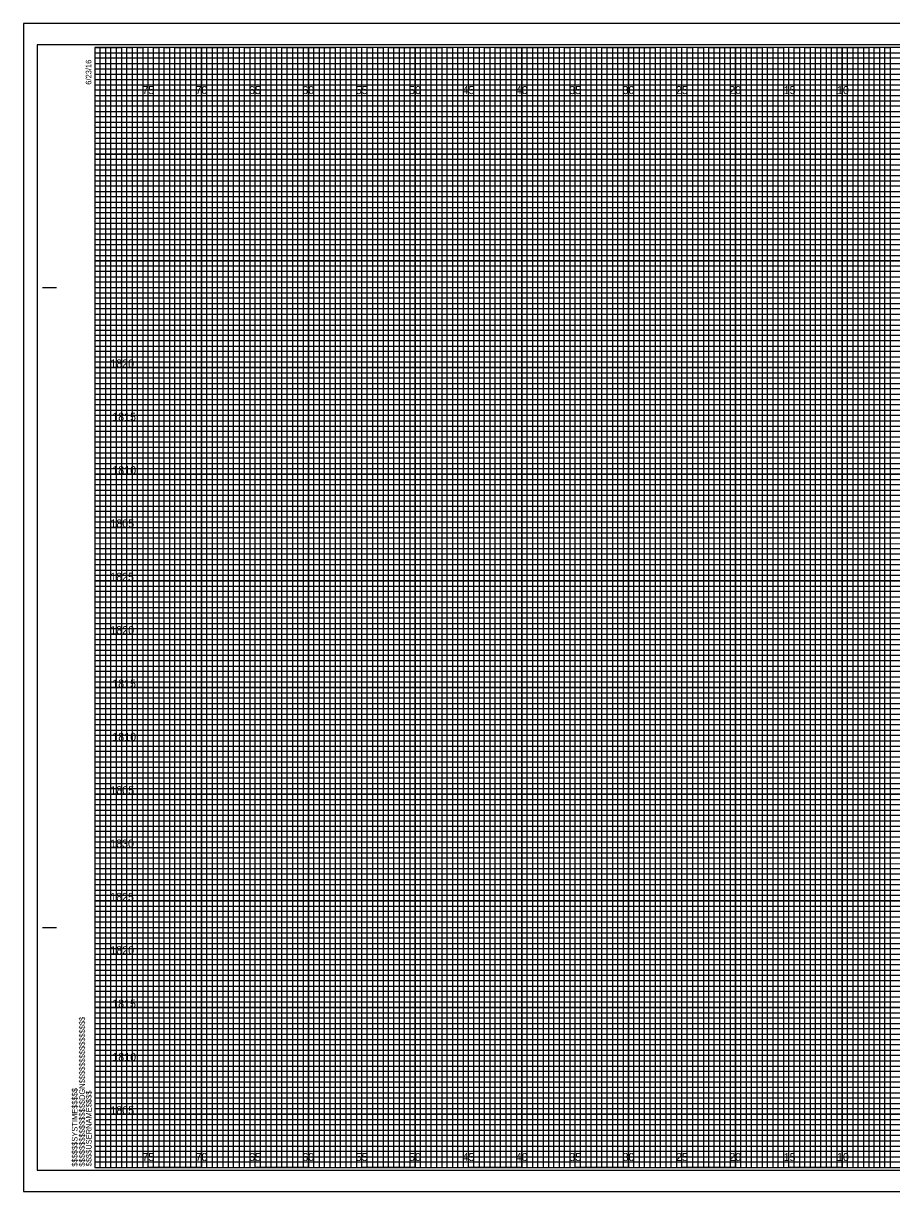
# Model space of a CAD drawing. Extents: x -7 to 392, y -2 to 440.
# Drawn here: x -6.7 to 74.6, y -2.3 to 107.3 of the extents above; entities that cross this region are included whole.
import ezdxf

# ---------------------------------------------------------------- set-up
doc = ezdxf.new("R2010")
doc.units = 0
for name, color, linetype in [('Prop Grid Mask', 7, 'Continuous'), ('Prop XS Elevation Labels', 7, 'Continuous'), ('Sheet Cross Section CELL', 7, 'Continuous'), ('Sheet Cross Section Grid Major CELL', 7, 'Continuous'), ('Sheet Cross Section Grid Middle CELL', 7, 'Continuous'), ('Sheet Cross Section Grid Minor 1 CELL', 7, 'Continuous'), ('Sheet Cross Section Grid Minor 2 CELL', 7, 'Continuous'), ('Sheet Cutting Line CELL', 7, 'Continuous'), ('Sheet DOT Grid CELL', 7, 'Continuous'), ('Sheet Plot Border Inside CELL', 7, 'Continuous'), ('Sheet Plot Border Outside CELL', 7, 'Continuous')]:
    doc.layers.add(name, color=color, linetype=linetype)

msp = doc.modelspace()

# ---------------------------------------------------------------- linework, layer by layer
at = {"layer": 'Sheet Cross Section CELL'}
for p, q in [((-4.9, 82.5), (-3.65, 82.5)), ((-4.85, 82.5), (-3.6, 82.5)), ((-4.9, 22.5), (-3.65, 22.5)), ((-4.85, 22.5), (-3.6, 22.5)), ((0, 0), (0, 0)), ((0, 0), (0, 0)), ((0, 0), (0, 0)), ((0, 0), (0, 0)), ((0, 0), (0, 0)), ((0, 0), (0, 0)), ((0, 0), (0, 0))]:
    msp.add_line(p, q, dxfattribs=at)
msp.add_lwpolyline([(160, 105), (0, 105), (0, 0), (160, 0)], close=True, dxfattribs=at)
at = {"layer": 'Sheet Cross Section Grid Major CELL'}
for p, q in [((5, 105), (0, 105)), ((5, 0), (5, 105)), ((15, 105), (10, 105)), ((10, 105), (10, 0)), ((15, 0), (15, 105)), ((25, 105), (20, 105)), ((20, 105), (20, 0)), ((25, 0), (25, 105)), ((35, 105), (30, 105)), ((30, 105), (30, 0)), ((35, 0), (35, 105)), ((45, 105), (40, 105)), ((40, 105), (40, 0)), ((45, 0), (45, 105)), ((55, 105), (50, 105)), ((50, 105), (50, 0)), ((55, 0), (55, 105)), ((65, 105), (60, 105)), ((60, 105), (60, 0)), ((65, 0), (65, 105)), ((75, 105), (70, 105)), ((70, 105), (70, 0)), ((10, 0), (5, 0)), ((20, 0), (15, 0)), ((30, 0), (25, 0)), ((40, 0), (35, 0)), ((50, 0), (45, 0)), ((60, 0), (55, 0)), ((70, 0), (65, 0))]:
    msp.add_line(p, q, dxfattribs=at)
for points in [[(0, 100), (160, 100), (160, 95), (0, 95)], [(0, 90), (160, 90), (160, 85), (0, 85)], [(0, 80), (160, 80), (160, 75), (0, 75)], [(0, 70), (160, 70), (160, 65), (0, 65)], [(0, 60), (160, 60), (160, 55), (0, 55)], [(0, 50), (160, 50), (160, 45), (0, 45)], [(0, 40), (160, 40), (160, 35), (0, 35)], [(0, 30), (160, 30), (160, 25), (0, 25)], [(0, 20), (160, 20), (160, 15), (0, 15)], [(0, 10), (160, 10), (160, 5), (0, 5)]]:
    msp.add_lwpolyline(points, dxfattribs=at)
at = {"layer": 'Sheet Cross Section Grid Middle CELL'}
for points in [[(0, 105), (2.5, 105), (2.5, 0), (7.5, 0), (7.5, 105), (12.5, 105), (12.5, 0), (17.5, 0), (17.5, 105), (22.5, 105), (22.5, 0), (27.5, 0), (27.5, 105), (32.5, 105), (32.5, 0), (37.5, 0), (37.5, 105), (42.5, 105), (42.5, 0), (47.5, 0), (47.5, 105), (52.5, 105), (52.5, 0), (57.5, 0), (57.5, 105), (62.5, 105), (62.5, 0), (67.5, 0), (67.5, 105), (72.5, 105), (72.5, 0), (77.5, 0)], [(0, 102.5), (137.5, 102.5)], [(0, 92.5), (160, 92.5), (160, 97.5), (0, 97.5)], [(0, 82.5), (160, 82.5), (160, 87.5), (0, 87.5)], [(0, 72.5), (160, 72.5), (160, 77.5), (0, 77.5)], [(0, 62.5), (160, 62.5), (160, 67.5), (0, 67.5)], [(0, 52.5), (160, 52.5), (160, 57.5), (0, 57.5)], [(0, 42.5), (160, 42.5), (160, 47.5), (0, 47.5)], [(0, 32.5), (160, 32.5), (160, 37.5), (0, 37.5)], [(0, 22.5), (160, 22.5), (160, 27.5), (0, 27.5)], [(0, 12.5), (160, 12.5), (160, 17.5), (0, 17.5)], [(0, 2.5), (160, 2.5), (160, 7.5), (0, 7.5)]]:
    msp.add_lwpolyline(points, dxfattribs=at)
at = {"layer": 'Sheet Cross Section Grid Minor 1 CELL'}
for p, q in [((0, 104.5), (130, 104.5)), ((130, 103.99), (0, 103.99)), ((0, 103.99), (0, 103.5)), ((0, 103.5), (130, 103.5)), ((130, 102.95), (0, 102.95)), ((0, 102.95), (0, 102)), ((0, 102), (160, 102))]:
    msp.add_line(p, q, dxfattribs=at)
for points in [[(0, 101.5), (135, 101.5), (160, 101.5), (160, 101), (0, 101)], [(0, 100.5), (160, 100.5), (160, 99.5), (0, 99.5)], [(0, 99), (160, 99), (160, 98.5), (0, 98.49)], [(0, 98), (160, 98), (160, 97), (0, 97)], [(0, 96.5), (160, 96.5), (160, 96), (0, 96)], [(0, 95.5), (160, 95.5), (160, 94.5), (0, 94.5)], [(0, 94), (160, 94), (160, 93.5), (0, 93.5)], [(0, 93), (160, 93), (160, 92), (0, 92)], [(0, 91.5), (160, 91.5), (160, 91), (0, 91)], [(0, 90.5), (160, 90.5), (160, 89.5), (0, 89.5)], [(0, 89), (160, 89), (160, 88.5), (0, 88.5)], [(0, 88), (160, 88), (160, 86.98), (160, 86.5), (160, 86), (0, 86)], [(0, 87), (160, 87), (160, 86.5), (0, 86.5)], [(0, 85.5), (160, 85.5), (160, 84.5), (0, 84.52)], [(0, 84.52), (160, 84.5), (160, 84), (0, 84)], [(0, 83.5), (160, 83.5), (160, 83), (0, 83)], [(0, 82), (160, 82), (160, 81.5), (0, 81.5)], [(0, 81), (160, 81), (160, 80.5), (0, 80.5)], [(-0.04, 79.45), (160, 79.45), (160, 78.94), (-0.04, 78.94)], [(0, 78.5), (160, 78.5), (160, 78), (0, 78)], [(0, 77), (160, 77), (160, 76.5), (0, 76.5)], [(0, 76), (160, 76), (160, 75.5), (0, 75.5)], [(0, 74.5), (160, 74.5), (160, 74), (0, 74)], [(0, 73.5), (160, 73.5), (160, 73), (0, 73)], [(0, 72), (160, 72), (160, 71.5), (0, 71.5)], [(0, 71), (160, 71), (160, 70.5), (0, 70.5)], [(0, 69.5), (160, 69.5), (159.99, 68.99), (0, 69)], [(0, 68.5), (160, 68.5), (160, 68), (0, 68)], [(0, 67), (160, 67), (160, 66.5), (0, 66.5)], [(0, 66), (160, 66), (160, 65.5), (0, 65.5)], [(0, 64.5), (160, 64.5), (160, 64), (0, 64)], [(0, 63.5), (160, 63.5), (160, 63), (0, 63)], [(0, 62), (160, 62), (160, 61.5), (0, 61.5)], [(0, 61), (160, 61), (160, 60.5), (0, 60.5)], [(0, 59.5), (160, 59.5), (160, 59), (0, 59)], [(0, 58.5), (160.03, 58.45), (160, 58), (0, 58)], [(0, 57), (160, 57), (160, 56.5), (0, 56.5)], [(0, 56), (160, 56), (160, 55.5), (0, 55.5)], [(0, 54.5), (160, 54.5), (160, 54), (0, 54)], [(0, 53.5), (160, 53.5), (160, 53), (0, 53)], [(0, 52), (160, 52), (160, 51.5), (0, 51.5)], [(0, 51), (160, 51), (160, 50.5), (0, 50.5)], [(0, 49.5), (160, 49.5), (160, 49), (0, 49)], [(0, 48.5), (160, 48.5), (160, 48), (0, 48)], [(0, 47), (160, 47), (160, 46.5), (0, 46.5)], [(0, 46), (160, 46), (160, 45.5), (0, 45.5)], [(0, 44.5), (160, 44.5), (160, 44), (0, 44)], [(0, 43.5), (160, 43.5), (160, 43), (0, 43)], [(0, 42), (160, 42), (160, 41.5), (0, 41.5)], [(0, 41), (160, 41), (160, 40.5), (0, 40.5)], [(0, 39.5), (160, 39.5), (159.99, 38.99), (0, 39)], [(0, 38.5), (160, 38.5), (160, 38), (0, 38)], [(0, 37), (160, 37), (160, 36.5), (0, 36.5)], [(0, 36), (160, 36), (160, 35.5), (0, 35.5)], [(0, 34.5), (160, 34.5), (160, 34), (0, 34)], [(0, 33.5), (160, 33.5), (160, 33), (0, 33)], [(0, 32), (160, 32), (160, 31.5), (0, 31.5)], [(0, 31), (160, 31), (160, 30.5), (0, 30.5)], [(0, 29.5), (160, 29.5), (160, 29), (0, 29)], [(0, 28.5), (160.03, 28.46), (160, 28), (0, 28)], [(0, 27), (160, 27), (160, 26.5), (0, 26.5)], [(0, 26), (160, 26), (160, 25.5), (0, 25.5)], [(0, 24.5), (160, 24.5), (160, 24), (0, 24)], [(0, 23.5), (160, 23.5), (160, 23), (0, 23)], [(0, 22), (160, 22), (160, 21.5), (0, 21.5)], [(0, 21), (160, 21), (160, 20.5), (0, 20.5)], [(0, 19.5), (160, 19.5), (160, 19), (0, 19)], [(0, 18.5), (160, 18.5), (160, 18), (0, 18)], [(0, 17), (160, 17), (160, 16.5), (0, 16.5)], [(0, 16), (160, 16), (160, 15.5), (0, 15.5)], [(0, 14.5), (160, 14.5), (160, 14), (0, 14)], [(0, 13.5), (160, 13.5), (160, 13), (0, 13)], [(0, 12), (160, 12), (160, 11.5), (0, 11.5)], [(0, 11), (160, 11), (160, 10.5), (0, 10.5)], [(0, 9.5), (160, 9.5), (160, 9), (0, 9)], [(0, 8.5), (160, 8.5), (160, 8), (0, 8)], [(0, 7), (160, 7), (160, 6.5), (0, 6.5)], [(0, 6), (160, 6), (160, 5.5), (0, 5.5)], [(0, 4.5), (160, 4.5), (160, 4), (0, 4)], [(0, 3.5), (160, 3.5), (160, 3), (0, 3)], [(0, 2), (160, 2), (160, 1.5), (0, 1.5)], [(0, 1), (160, 1), (160, 0.5), (0, 0.5)]]:
    msp.add_lwpolyline(points, dxfattribs=at)
at = {"layer": 'Sheet Cross Section Grid Minor 2 CELL'}
for points in [[(0, 0), (0.5, 0), (0.5, 105), (1, 105), (1, 0)], [(1, 0), (1.5, 0), (1.5, 105), (2, 105), (2, 0)], [(2.5, 0), (3, 0), (3, 105), (3.5, 105), (3.5, 0)], [(3.5, 0), (4, 0), (4, 105), (4.5, 105), (4.5, 0)], [(5, 0), (5.5, 0), (5.5, 105), (6, 105), (6, 0)], [(6, 0), (6.5, 0), (6.5, 105), (7, 105), (7, 0)], [(7.5, 0), (8, 0), (8, 105), (8.5, 105), (8.5, 0)], [(8.5, 0), (9, 0), (9, 105), (9.5, 105), (9.5, 0)], [(10, 0), (10.5, 0), (10.5, 105), (11, 105), (11, 0)], [(11, 0), (11.5, 0), (11.5, 105), (12, 105), (12, 0)], [(12.5, 0), (13, 0), (13, 105), (13.5, 105), (13.5, 0)], [(13.5, 0), (14, 0), (14, 105), (14.5, 105), (14.5, 0)], [(15, 0), (15.5, 0), (15.5, 105), (16, 105), (16, 0)], [(16, 0), (16.5, 0), (16.5, 105), (17, 105), (17, 0)], [(17.5, 0), (18, 0), (18, 105), (18.5, 105), (18.5, 0)], [(18.5, 0), (19, 0), (19, 105), (19.5, 105), (19.5, 0)], [(20, 0), (20.5, 0), (20.5, 105), (21, 105), (21, 0)], [(21, 0), (21.5, 0), (21.5, 105), (22, 105), (22, 0)], [(22.5, 0), (23, 0), (23, 105), (23.5, 105), (23.5, 0)], [(23.5, 0), (24, 0), (24, 105), (24.5, 105), (24.5, 0)], [(25, 0), (25.5, 0), (25.5, 105), (26, 105), (26, 0)], [(26, 0), (26.5, 0), (26.5, 105), (27, 105), (27, 0)], [(27.5, 0), (28, 0), (28, 105), (28.5, 105), (28.5, 0)], [(28.5, 0), (29, 0), (29, 105), (29.5, 105), (29.5, 0)], [(30, 0), (30.5, 0), (30.5, 105), (31, 105), (31, 0)], [(31, 0), (31.5, 0), (31.5, 105), (32, 105), (32, 0)], [(32.5, 0), (33, 0), (33, 105), (33.5, 105), (33.5, 0)], [(33.5, 0), (34, 0), (34, 105), (34.5, 105), (34.5, 0)], [(35, 0), (35.5, 0), (35.5, 105), (36, 105), (36, 0)], [(36, 0), (36.5, 0), (36.5, 105), (37, 105), (37, 0)], [(37.5, 0), (38, 0), (38, 105), (38.5, 105), (38.5, 0)], [(38.5, 0), (39, 0), (39, 105), (39.5, 105), (39.5, 0)], [(40, 0), (40.5, 0), (40.5, 105), (41, 105), (41, 0)], [(41, 0), (41.5, 0), (41.5, 105), (42, 105), (42, 0)], [(42.5, 0), (43, 0), (43, 105), (43.5, 105), (43.5, 0)], [(43.5, 0), (44, 0), (44, 105), (44.5, 105), (44.5, 0)], [(45, 0), (45.5, 0), (45.5, 105), (46, 105), (46, 0)], [(46, 0), (46.5, 0), (46.5, 105), (47, 105), (47, 0)], [(47.5, 0), (48, 0), (48, 105), (48.5, 105), (48.5, 0)], [(48.5, 0), (49, 0), (49, 105), (49.5, 105), (49.5, 0)], [(50, 0), (50.5, 0), (50.5, 105), (51, 105), (51, 0)], [(51, 0), (51.5, 0), (51.5, 105), (52, 105), (52, 0)], [(52.5, 0), (53, 0), (53, 105), (53.5, 105), (53.5, 0)], [(53.5, 0), (54, 0), (54, 105), (54.5, 105), (54.5, 0)], [(55, 0), (55.5, 0), (55.5, 105), (56, 105), (56, 0)], [(56, 0), (56.5, 0), (56.5, 105), (57, 105), (57, 0)], [(57.5, 0), (58, 0), (58, 105), (58.5, 105), (58.5, 0)], [(58.5, 0), (59, 0), (59, 105), (59.5, 105), (59.5, 0)], [(60, 0), (60.5, 0), (60.5, 105), (61, 105), (61, 0)], [(61, 0), (61.5, 0), (61.5, 105), (62, 105), (62, 0)], [(62.5, 0), (63, 0), (63, 105), (63.5, 105), (63.5, 0)], [(63.5, 0), (64, 0), (64, 105), (64.5, 105), (64.5, 0)], [(65, 0), (65.5, 0), (65.5, 105), (66, 105), (66, 0)], [(66, 0), (66.5, 0), (66.5, 105), (67, 105), (67, 0)], [(67.5, 0), (68, 0), (68, 105), (68.5, 105), (68.5, 0)], [(68.5, 0), (69, 0), (69, 105), (69.5, 105), (69.5, 0)], [(70, 0), (70.5, 0), (70.5, 105), (71, 105), (71, 0)], [(71, 0), (71.5, 0), (71.5, 105), (72, 105), (72, 0)], [(72.5, 0), (73, 0), (73, 105), (73.5, 105), (73.5, 0)], [(73.5, 0), (74, 0), (74, 105), (74.5, 105), (74.5, 0)]]:
    msp.add_lwpolyline(points, dxfattribs=at)
at = {"layer": 'Sheet Cutting Line CELL'}
for p, q in [((161.65, 107.25), (-6.7, 107.25)), ((-6.7, 107.25), (-6.7, -2.25)), ((-6.7, -2.25), (161.65, -2.25))]:
    msp.add_line(p, q, dxfattribs=at)
at = {"layer": 'Sheet DOT Grid CELL'}
for p, q in [((5, 0), (5, 105)), ((10, 0), (10, 105)), ((15, 0), (15, 105)), ((20, 0), (20, 105)), ((25, 0), (25, 105)), ((30, 0), (30, 105)), ((35, 0), (35, 105)), ((40, 0), (40, 105)), ((45, 0), (45, 105)), ((50, 0), (50, 105)), ((55, 0), (55, 105)), ((60, 0), (60, 105)), ((65, 0), (65, 105)), ((70, 0), (70, 105)), ((0, 100), (160, 100)), ((0, 95), (160, 95)), ((0, 90), (160, 90)), ((0, 85), (160, 85)), ((0, 80), (160, 80)), ((0, 75), (160, 75)), ((0, 70), (160, 70)), ((0, 65), (160, 65)), ((0, 60), (160, 60)), ((0, 55), (160, 55)), ((0, 50), (160, 50)), ((0, 45), (160, 45)), ((0, 40), (160, 40)), ((0, 35), (160, 35)), ((0, 30), (160, 30)), ((0, 25), (160, 25)), ((0, 20), (160, 20)), ((0, 15), (160, 15)), ((0, 10), (160, 10)), ((0, 5), (160, 5))]:
    msp.add_line(p, q, dxfattribs=at)
at = {"layer": 'Sheet Plot Border Inside CELL'}
msp.add_lwpolyline([(-5.4, -0.25), (161.2, -0.25), (161.2, 105.25), (-5.4, 105.25)], close=True, dxfattribs=at)
at = {"layer": 'Sheet Plot Border Outside CELL'}
msp.add_lwpolyline([(-6.7, -2.25), (161.65, -2.25), (161.65, 107.25), (-6.7, 107.25)], close=True, dxfattribs=at)

# ---------------------------------------------------------------- texts
at = {"layer": 'Prop Grid Mask'}
for s, p in [('75', (4.44, 100.62)), ('70', (9.43, 100.62)), ('65', (14.44, 100.62)), ('60', (19.43, 100.62)), ('55', (24.44, 100.62)), ('50', (29.43, 100.62)), ('45', (34.44, 100.62)), ('40', (39.43, 100.62)), ('35', (44.44, 100.62)), ('30', (49.43, 100.62)), ('25', (54.44, 100.62)), ('20', (59.43, 100.62)), ('15', (64.53, 100.62)), ('10', (69.52, 100.62)), ('75', (4.44, 0.62)), ('70', (9.43, 0.62)), ('65', (14.44, 0.62)), ('60', (19.43, 0.62)), ('55', (24.44, 0.62)), ('50', (29.43, 0.62)), ('45', (34.44, 0.62)), ('40', (39.43, 0.62)), ('35', (44.44, 0.62)), ('30', (49.43, 0.62)), ('25', (54.44, 0.62)), ('20', (59.43, 0.62)), ('15', (64.53, 0.62)), ('10', (69.52, 0.62))]:
    msp.add_text(s, height=0.75, dxfattribs=at).set_placement(p)
at = {"layer": 'Prop XS Elevation Labels'}
for s, p in [('1820', (1.44, 75)), ('1815', (1.62, 70)), ('1810', (1.63, 65)), ('1805', (1.45, 60)), ('1825', (1.43, 55)), ('1820', (1.44, 50)), ('1815', (1.62, 45)), ('1810', (1.63, 40)), ('1805', (1.45, 35)), ('1830', (1.43, 30)), ('1825', (1.43, 25)), ('1820', (1.44, 20)), ('1815', (1.62, 15)), ('1810', (1.63, 10)), ('1805', (1.45, 5))]:
    msp.add_text(s, height=0.75, dxfattribs=at).set_placement(p)
at = {"layer": 'Sheet Cross Section CELL'}
for s, p in [('6/23/16', (-0.33, 101.5)), ('$$$$$$$$$$$$$$$$DGN$$$$$$$$$$$$$$$$', (-0.94, 0.09)), ('$$$$$$SYSTIME$$$$$', (-1.63, 0.09)), ('$$$$USERNAME$$$$', (-0.31, 0.12))]:
    msp.add_text(s, height=0.525, rotation=90, dxfattribs=at).set_placement(p)

doc.saveas('drawing.dxf')
